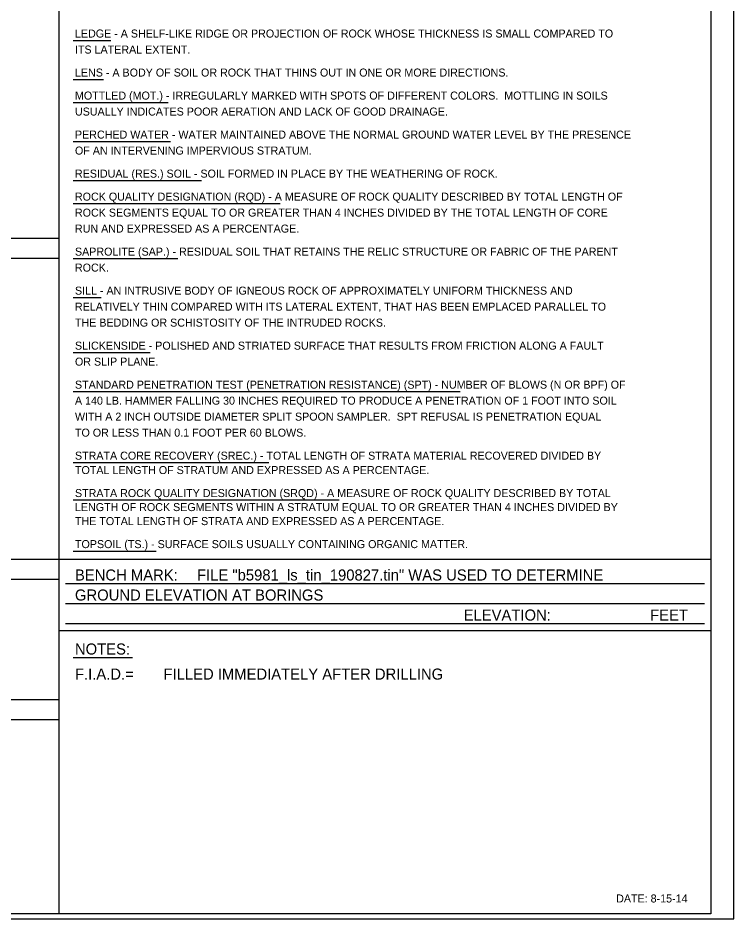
# Model space of a CAD drawing. Extents: x 265553 to 275568, y 168312 to 173522.
# Drawn here: x 268044.8 to 268432.9, y 170247.1 to 170735.3 of the extents above; entities that cross this region are included whole.
import ezdxf

# ---------------------------------------------------------------- set-up
doc = ezdxf.new("R2010")
doc.units = 0
doc.layers.add('Geotech Sheets and Borders Cell', color=7, linetype='Continuous')
doc.layers.add('Sheet Plot Border Inside CELL', color=7, linetype='Continuous')

msp = doc.modelspace()

# ---------------------------------------------------------------- linework, layer by layer
at = {"layer": 'Geotech Sheets and Borders Cell'}
for p, q in [((268066.96, 171052.08), (268066.96, 170249.94)), ((268074.77, 170723.18), (268095.24, 170723.18)), ((268074.77, 170702.04), (268091.26, 170702.04)), ((268074.77, 170689.56), (268126.29, 170689.56)), ((268074.77, 170668.42), (268127.54, 170668.42)), ((268074.77, 170647.28), (268144.3, 170647.28)), ((268074.77, 170634.81), (268186.85, 170634.81)), ((267670.42, 170616.07), (268066.96, 170616.07)), ((267670.42, 170605.22), (268066.96, 170605.22)), ((268074.77, 170605), (268131.49, 170605)), ((268074.77, 170583.86), (268089.91, 170583.86)), ((268074.77, 170554.05), (268116.43, 170554.05)), ((268074.77, 170532.91), (268284.52, 170532.91)), ((268074.77, 170494.44), (268180.81, 170494.44)), ((268074.77, 170474.16), (268218.83, 170474.16)), ((268074.77, 170446.5), (268119.74, 170446.5)), ((268420.42, 170441.94), (267670.42, 170441.94)), ((268066.96, 170431.1), (267670.42, 170431.1)), ((268070.52, 170428.92), (268416.86, 170428.92)), ((268070.52, 170418.07), (268416.86, 170418.07)), ((268070.52, 170407.22), (268416.86, 170407.22)), ((268066.96, 170403.41), (268420.42, 170403.41)), ((268074.77, 170388.82), (268106.98, 170388.82)), ((268066.96, 170365.94), (267670.42, 170365.94)), ((268066.96, 170355.1), (267670.42, 170355.1))]:
    msp.add_line(p, q, dxfattribs=at)
msp.add_lwpolyline([(266920.42, 171299.94), (268420.42, 171299.94), (268420.42, 170249.94), (266920.42, 170249.94)], close=True, dxfattribs=at)
at = {"layer": 'Sheet Plot Border Inside CELL'}
msp.add_lwpolyline([(266765.25, 170247.11), (268432.92, 170247.11), (268432.92, 171302.77), (266765.25, 171302.77)], close=True, dxfattribs=at)

# ---------------------------------------------------------------- texts
at = {"layer": 'Geotech Sheets and Borders Cell'}
for s, height, p in [('LEDGE - A SHELF-LIKE RIDGE OR PROJECTION OF ROCK WHOSE THICKNESS IS SMALL COMPARED TO', 4.3381, (268075.71, 170724.76)), ('ITS LATERAL EXTENT.', 4.3381, (268075.71, 170716.09)), ('LENS - A BODY OF SOIL OR ROCK THAT THINS OUT IN ONE OR MORE DIRECTIONS.', 4.3381, (268075.71, 170703.62)), ('MOTTLED (MOT.) - IRREGULARLY MARKED WITH SPOTS OF DIFFERENT COLORS.  MOTTLING IN SOILS', 4.3381, (268075.71, 170691.15)), ('USUALLY INDICATES POOR AERATION AND LACK OF GOOD DRAINAGE.', 4.3381, (268075.71, 170682.48)), ('PERCHED WATER - WATER MAINTAINED ABOVE THE NORMAL GROUND WATER LEVEL BY THE PRESENCE', 4.3381, (268075.71, 170670)), ('OF AN INTERVENING IMPERVIOUS STRATUM.', 4.3381, (268075.71, 170661.34)), ('RESIDUAL (RES.) SOIL - SOIL FORMED IN PLACE BY THE WEATHERING OF ROCK.', 4.3381, (268075.71, 170648.86)), ('ROCK QUALITY DESIGNATION (RQD) - A MEASURE OF ROCK QUALITY DESCRIBED BY TOTAL LENGTH OF ', 4.3381, (268075.71, 170636.39)), ('ROCK SEGMENTS EQUAL TO OR GREATER THAN 4 INCHES DIVIDED BY THE TOTAL LENGTH OF CORE', 4.3381, (268075.71, 170627.72)), ('RUN AND EXPRESSED AS A PERCENTAGE.', 4.3381, (268075.71, 170619.06)), ('SAPROLITE (SAP.) - RESIDUAL SOIL THAT RETAINS THE RELIC STRUCTURE OR FABRIC OF THE PARENT', 4.3381, (268075.71, 170606.58)), ('ROCK.', 4.338, (268075.71, 170597.92)), ('SILL - AN INTRUSIVE BODY OF IGNEOUS ROCK OF APPROXIMATELY UNIFORM THICKNESS AND', 4.3381, (268075.71, 170585.44)), ('RELATIVELY THIN COMPARED WITH ITS LATERAL EXTENT, THAT HAS BEEN EMPLACED PARALLEL TO', 4.3381, (268075.71, 170576.77)), ('THE BEDDING OR SCHISTOSITY OF THE INTRUDED ROCKS.', 4.3381, (268075.71, 170568.11)), ('SLICKENSIDE - POLISHED AND STRIATED SURFACE THAT RESULTS FROM FRICTION ALONG A FAULT', 4.3381, (268075.71, 170555.63)), ('OR SLIP PLANE.', 4.3381, (268075.71, 170546.97)), ('STANDARD PENETRATION TEST (PENETRATION RESISTANCE) (SPT) - NUMBER OF BLOWS (N OR BPF) OF ', 4.3381, (268075.71, 170534.49)), ('A 140 LB. HAMMER FALLING 30 INCHES REQUIRED TO PRODUCE A PENETRATION OF 1 FOOT INTO SOIL', 4.3381, (268075.71, 170525.83)), ('WITH A 2 INCH OUTSIDE DIAMETER SPLIT SPOON SAMPLER.  SPT REFUSAL IS PENETRATION EQUAL', 4.3381, (268075.71, 170517.16)), ('TO OR LESS THAN 0.1 FOOT PER 60 BLOWS.', 4.3381, (268075.71, 170508.49)), ('STRATA CORE RECOVERY (SREC.) - TOTAL LENGTH OF STRATA MATERIAL RECOVERED DIVIDED BY', 4.3381, (268075.71, 170496.02)), ('TOTAL LENGTH OF STRATUM AND EXPRESSED AS A PERCENTAGE.', 4.3381, (268075.71, 170488.21)), ('STRATA ROCK QUALITY DESIGNATION (SRQD) - A MEASURE OF ROCK QUALITY DESCRIBED BY TOTAL', 4.3381, (268075.71, 170475.74)), ('LENGTH OF ROCK SEGMENTS WITHIN A STRATUM EQUAL TO OR GREATER THAN 4 INCHES DIVIDED BY', 4.3381, (268075.71, 170468.14)), ('THE TOTAL LENGTH OF STRATA AND EXPRESSED AS A PERCENTAGE.', 4.3381, (268075.71, 170460.55)), ('TOPSOIL (TS.) - SURFACE SOILS USUALLY CONTAINING ORGANIC MATTER.', 4.3381, (268075.71, 170448.08)), ('BENCH MARK:', 6, (268075.71, 170430.51)), ('FILE "b5981_ls_tin_190827.tin" WAS USED TO DETERMINE ', 6, (268141.85, 170430.51)), ('GROUND ELEVATION AT BORINGS', 6, (268075.71, 170419.66)), ('ELEVATION:', 6, (268286.39, 170408.81)), ('FEET', 6, (268387.45, 170408.81)), ('NOTES:', 6, (268075.71, 170390.4)), ('F.I.A.D.= ', 6, (268075.71, 170376.82)), ('FILLED IMMEDIATELY AFTER DRILLING', 6, (268123.71, 170376.82)), ('DATE: 8-15-14', 4.3381, (268369.05, 170256.05))]:
    msp.add_text(s, height=height, dxfattribs=at).set_placement(p)

doc.saveas('drawing.dxf')
